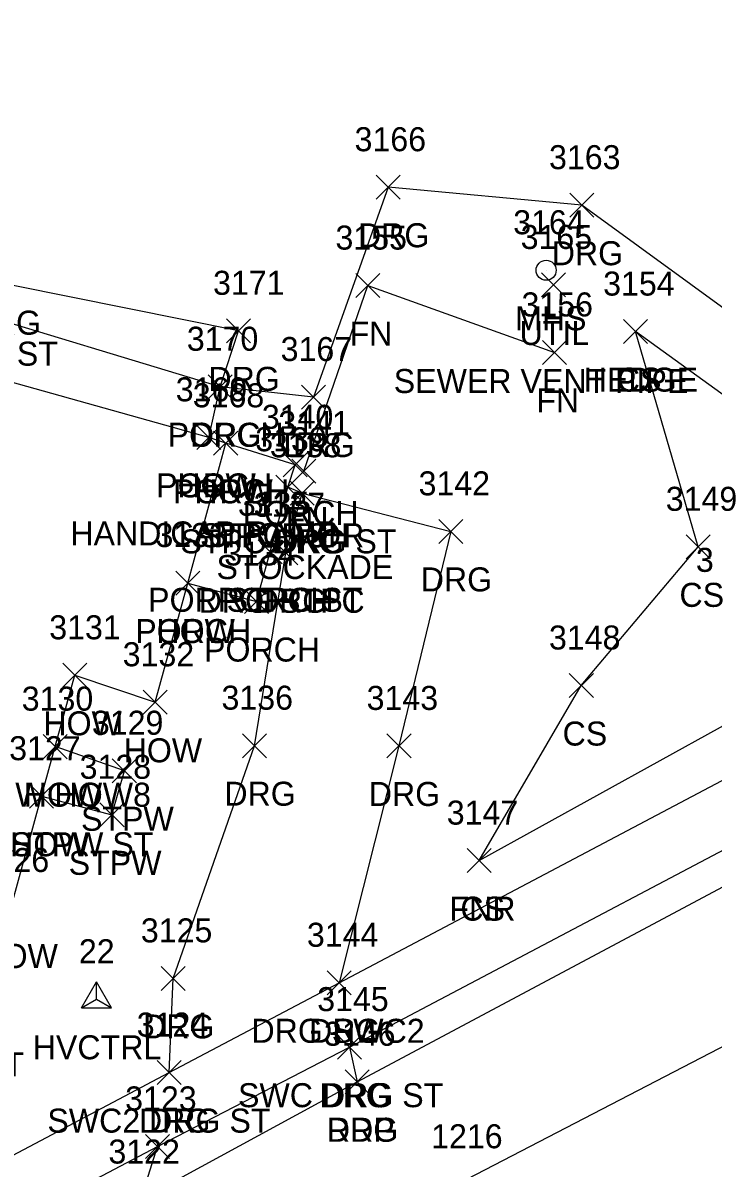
# Model space of a CAD drawing. Extents: x 1477930 to 1480780, y 774090 to 784647.
# Drawn here: x 1479519.5 to 1479576.9, y 774762.5 to 774857.9 of the extents above; entities that cross this region are included whole.
import ezdxf

# ---------------------------------------------------------------- set-up
doc = ezdxf.new("R2010")
doc.units = 0
for name, color, linetype in [('C_A', 7, 'Continuous'), ('C_I', 7, 'Continuous'), ('CPSM', 7, 'Continuous'), ('L_A', 7, 'Continuous'), ('L_C', 7, 'Continuous'), ('L_I', 7, 'Continuous'), ('L_TIC', 7, 'Continuous'), ('LAHR', 7, 'Continuous'), ('LBC', 7, 'Continuous'), ('LBF', 7, 'Continuous'), ('LELB', 7, 'Continuous'), ('LFNC', 7, 'Continuous'), ('P_A', 7, 'Continuous'), ('P_I', 7, 'Continuous'), ('P_TIC', 7, 'Continuous'), ('PET', 7, 'Continuous'), ('PRC', 7, 'Continuous'), ('R_A', 7, 'Continuous'), ('R_I', 7, 'Continuous'), ('R_TIC', 7, 'Continuous'), ('RDG', 7, 'Continuous'), ('RSW', 7, 'Continuous'), ('U_A', 7, 'Continuous'), ('U_C', 7, 'Continuous'), ('U_I', 7, 'Continuous'), ('UDEFAULT', 7, 'Continuous'), ('USMH', 7, 'Continuous')]:
    doc.layers.add(name, color=color, linetype=linetype)

msp = doc.modelspace()

# ---------------------------------------------------------------- linework, layer by layer
at = {"layer": 'CPSM'}
for p, q in [((1479524.324, 774775.847), (1479525.574, 774778.012)), ((1479526.824, 774775.847), (1479525.574, 774778.012)), ((1479525.574, 774776.568), (1479525.574, 774778.012)), ((1479524.324, 774775.847), (1479525.574, 774776.568)), ((1479525.574, 774776.568), (1479525.574, 774776.568)), ((1479525.574, 774776.568), (1479526.824, 774775.847)), ((1479524.324, 774775.847), (1479526.824, 774775.847))]:
    msp.add_line(p, q, dxfattribs=at)
at = {"layer": 'L_TIC'}
for points in [[(1479547.155, 774835.01), (1479549.155, 774837.01)], [(1479549.155, 774835.01), (1479547.155, 774837.01)], [(1479569.436, 774831.18), (1479571.436, 774833.18)], [(1479571.436, 774831.18), (1479569.436, 774833.18)], [(1479569.436, 774831.18), (1479571.436, 774833.18)], [(1479571.436, 774831.18), (1479569.436, 774833.18)], [(1479562.695, 774829.443), (1479564.695, 774831.443)], [(1479564.695, 774829.443), (1479562.695, 774831.443)], [(1479534.871, 774826.584), (1479536.871, 774828.584)], [(1479536.871, 774826.584), (1479534.871, 774828.584)], [(1479533.918, 774822.368), (1479535.918, 774824.368)], [(1479535.918, 774822.368), (1479533.918, 774824.368)], [(1479533.918, 774822.368), (1479535.918, 774824.368)], [(1479535.918, 774822.368), (1479533.918, 774824.368)], [(1479535.326, 774821.874), (1479537.326, 774823.874)], [(1479537.326, 774821.874), (1479535.326, 774823.874)], [(1479535.326, 774821.874), (1479537.326, 774823.874)], [(1479537.326, 774821.874), (1479535.326, 774823.874)], [(1479541.115, 774820.083), (1479543.115, 774822.083)], [(1479543.115, 774820.083), (1479541.115, 774822.083)], [(1479541.837, 774819.567), (1479543.837, 774821.567)], [(1479543.837, 774819.567), (1479541.837, 774821.567)], [(1479540.488, 774818.212), (1479542.488, 774820.212)], [(1479542.488, 774818.212), (1479540.488, 774820.212)], [(1479540.488, 774818.212), (1479542.488, 774820.212)], [(1479542.488, 774818.212), (1479540.488, 774820.212)], [(1479541.697, 774817.711), (1479543.697, 774819.711)], [(1479543.697, 774817.711), (1479541.697, 774819.711)], [(1479539.037, 774812.838), (1479541.037, 774814.838)], [(1479541.037, 774812.838), (1479539.037, 774814.838)], [(1479539.037, 774812.838), (1479541.037, 774814.838)], [(1479541.037, 774812.838), (1479539.037, 774814.838)], [(1479540.344, 774812.755), (1479542.344, 774814.755)], [(1479542.344, 774812.755), (1479540.344, 774814.755)], [(1479574.655, 774813.252), (1479576.655, 774815.252)], [(1479576.655, 774813.252), (1479574.655, 774815.252)], [(1479532.175, 774810.235), (1479534.175, 774812.235)], [(1479534.175, 774810.235), (1479532.175, 774812.235)], [(1479532.175, 774810.235), (1479534.175, 774812.235)], [(1479534.175, 774810.235), (1479532.175, 774812.235)], [(1479537.903, 774808.696), (1479539.903, 774810.696)], [(1479539.903, 774808.696), (1479537.903, 774810.696)], [(1479522.767, 774802.55), (1479524.767, 774804.55)], [(1479524.767, 774802.55), (1479522.767, 774804.55)], [(1479564.927, 774801.699), (1479566.927, 774803.699)], [(1479566.927, 774801.699), (1479564.927, 774803.699)], [(1479529.448, 774800.304), (1479531.448, 774802.304)], [(1479531.448, 774800.304), (1479529.448, 774802.304)], [(1479521.131, 774796.607), (1479523.131, 774798.607)], [(1479523.131, 774796.607), (1479521.131, 774798.607)], [(1479521.131, 774796.607), (1479523.131, 774798.607)], [(1479523.131, 774796.607), (1479521.131, 774798.607)], [(1479526.892, 774794.601), (1479528.892, 774796.601)], [(1479528.892, 774794.601), (1479526.892, 774796.601)], [(1479520, 774792.48), (1479522, 774794.48)], [(1479522, 774792.48), (1479520, 774794.48)], [(1479520, 774792.48), (1479522, 774794.48)], [(1479522, 774792.48), (1479520, 774794.48)], [(1479525.864, 774790.931), (1479527.864, 774792.931)], [(1479527.864, 774790.931), (1479525.864, 774792.931)], [(1479556.42, 774787.114), (1479558.42, 774789.114)], [(1479558.42, 774787.114), (1479556.42, 774789.114)], [(1479556.42, 774787.114), (1479558.42, 774789.114)], [(1479558.42, 774787.114), (1479556.42, 774789.114)]]:
    msp.add_lwpolyline(points, dxfattribs=at)
at = {"layer": 'LAHR'}
msp.add_lwpolyline([(1479584.946, 774821.703), (1479570.436, 774832.18)], dxfattribs=at)
at = {"layer": 'LBC'}
msp.add_lwpolyline([(1479518.439, 774784.168), (1479521, 774793.48), (1479522.131, 774797.607), (1479523.767, 774803.55), (1479530.448, 774801.304), (1479533.175, 774811.235), (1479536.326, 774822.874), (1479534.918, 774823.368), (1479506.67, 774831.282), (1479500.925, 774832.917)], dxfattribs=at)
at = {"layer": 'LBF'}
for points in [[(1479534.918, 774823.368), (1479535.871, 774827.584), (1479513.492, 774834.341), (1479508.389, 774836.064), (1479506.67, 774831.282)], [(1479533.175, 774811.235), (1479538.903, 774809.696), (1479540.037, 774813.838), (1479541.488, 774819.212), (1479542.115, 774821.083), (1479536.326, 774822.874)], [(1479540.037, 774813.838), (1479541.344, 774813.755), (1479542.697, 774818.711), (1479541.488, 774819.212)], [(1479521, 774793.48), (1479526.864, 774791.931), (1479527.892, 774795.601), (1479522.131, 774797.607)]]:
    msp.add_lwpolyline(points, dxfattribs=at)
at = {"layer": 'LELB'}
msp.add_lwpolyline([(1479557.42, 774788.114), (1479565.927, 774802.699), (1479575.655, 774814.252), (1479570.436, 774832.18)], dxfattribs=at)
at = {"layer": 'LFNC'}
for points in [[(1479542.837, 774820.567), (1479548.155, 774836.01), (1479563.695, 774830.443)], [(1479557.42, 774788.114), (1479582.544, 774801.997)]]:
    msp.add_lwpolyline(points, dxfattribs=at)
at = {"layer": 'P_TIC'}
for points in [[(1479546.258, 774768.694), (1479548.258, 774770.694)], [(1479548.258, 774768.694), (1479546.258, 774770.694)]]:
    msp.add_lwpolyline(points, dxfattribs=at)
at = {"layer": 'PET'}
msp.add_lwpolyline([(1479458.85, 774725.87), (1479463.751, 774725.492), (1479503.779, 774746.035), (1479529.26, 774759.882), (1479547.258, 774769.694), (1479593.154, 774794.187), (1479638.489, 774817.325), (1479672.216, 774835.12), (1479713.57, 774857.959), (1479753.195, 774879.739), (1479794.614, 774902.456), (1479830.334, 774920.879), (1479861.739, 774937.834), (1479877.763, 774946.853), (1479905.129, 774960.917), (1479936.646, 774977.614), (1479958.815, 774989.405), (1479973.001, 774995.932), (1480008.349, 775014.945)], dxfattribs=at)
at = {"layer": 'PRC'}
msp.add_lwpolyline([(1480015.885, 775005.874), (1479971.787, 774982.459), (1479929.137, 774959.029), (1479892.607, 774942.344), (1479860.439, 774925.31), (1479806.486, 774896.537), (1479658.454, 774815.543), (1479643.753, 774807.567), (1479597.617, 774782.971), (1479555.607, 774761.155), (1479513.424, 774740.323), (1479470.998, 774718.599), (1479432.732, 774701.096), (1479418.317, 774694.969), (1479344.833, 774660.922), (1479298.596, 774640.387), (1479262.123, 774624.397), (1479219.633, 774609.006), (1479186.742, 774593.828)], dxfattribs=at)
at = {"layer": 'R_TIC'}
for points in [[(1479548.849, 774843.203), (1479550.849, 774845.203)], [(1479550.849, 774843.203), (1479548.849, 774845.203)], [(1479564.978, 774841.708), (1479566.978, 774843.708)], [(1479566.978, 774841.708), (1479564.978, 774843.708)], [(1479536.401, 774831.244), (1479538.401, 774833.244)], [(1479538.401, 774831.244), (1479536.401, 774833.244)], [(1479534.871, 774826.584), (1479536.871, 774828.584)], [(1479536.871, 774826.584), (1479534.871, 774828.584)], [(1479542.643, 774825.727), (1479544.643, 774827.727)], [(1479544.643, 774825.727), (1479542.643, 774827.727)], [(1479541.697, 774817.711), (1479543.697, 774819.711)], [(1479543.697, 774817.711), (1479541.697, 774819.711)], [(1479554.073, 774814.54), (1479556.073, 774816.54)], [(1479556.073, 774814.54), (1479554.073, 774816.54)], [(1479540.344, 774812.755), (1479542.344, 774814.755)], [(1479542.344, 774812.755), (1479540.344, 774814.755)], [(1479537.727, 774796.688), (1479539.727, 774798.688)], [(1479539.727, 774796.688), (1479537.727, 774798.688)], [(1479549.751, 774796.668), (1479551.751, 774798.668)], [(1479551.751, 774796.668), (1479549.751, 774798.668)], [(1479530.959, 774777.305), (1479532.959, 774779.305)], [(1479532.959, 774777.305), (1479530.959, 774779.305)], [(1479544.779, 774776.94), (1479546.779, 774778.94)], [(1479546.779, 774776.94), (1479544.779, 774778.94)], [(1479544.779, 774776.94), (1479546.779, 774778.94)], [(1479546.779, 774776.94), (1479544.779, 774778.94)], [(1479545.637, 774771.577), (1479547.637, 774773.577)], [(1479547.637, 774771.577), (1479545.637, 774773.577)], [(1479545.637, 774771.577), (1479547.637, 774773.577)], [(1479547.637, 774771.577), (1479545.637, 774773.577)], [(1479530.618, 774769.459), (1479532.618, 774771.459)], [(1479532.618, 774769.459), (1479530.618, 774771.459)], [(1479530.618, 774769.459), (1479532.618, 774771.459)], [(1479532.618, 774769.459), (1479530.618, 774771.459)], [(1479546.258, 774768.694), (1479548.258, 774770.694)], [(1479548.258, 774768.694), (1479546.258, 774770.694)], [(1479529.653, 774763.307), (1479531.653, 774765.307)], [(1479531.653, 774763.307), (1479529.653, 774765.307)], [(1479529.653, 774763.307), (1479531.653, 774765.307)], [(1479531.653, 774763.307), (1479529.653, 774765.307)]]:
    msp.add_lwpolyline(points, dxfattribs=at)
at = {"layer": 'RDG'}
for points in [[(1479598.757, 774810.291), (1479588.804, 774826.084), (1479565.978, 774842.708), (1479549.849, 774844.203), (1479543.643, 774826.727), (1479535.871, 774827.584), (1479537.401, 774832.244), (1479514.065, 774836.924)], [(1479542.697, 774818.711), (1479555.073, 774815.54), (1479550.751, 774797.668), (1479545.779, 774777.94)], [(1479531.618, 774770.459), (1479531.959, 774778.305), (1479538.727, 774797.688), (1479541.344, 774813.755)], [(1479546.637, 774772.577), (1479547.258, 774769.694)], [(1479529.26, 774759.882), (1479530.653, 774764.307)]]:
    msp.add_lwpolyline(points, dxfattribs=at)
at = {"layer": 'RSW'}
for points in [[(1479454.048, 774732.201), (1479457.362, 774735.507), (1479461.547, 774734.407), (1479499.972, 774753.705), (1479531.618, 774770.459), (1479545.779, 774777.94), (1479596.697, 774804.864), (1479626.336, 774821.051), (1479665.838, 774842.34), (1479709.717, 774866.291), (1479748.232, 774887.235), (1479790.979, 774910.551), (1479825.884, 774929.42), (1479857.892, 774946.347), (1479880.805, 774958.363), (1479898.018, 774967.807), (1479932.308, 774985.558), (1479966.418, 775003.673), (1480005.027, 775023.737)], [(1479458.85, 774725.87), (1479459.6, 774730.001), (1479502.041, 774749.228), (1479530.653, 774764.307), (1479546.637, 774772.577), (1479592.504, 774796.776), (1479632.83, 774818.633), (1479668.395, 774838.36), (1479711.894, 774862.209), (1479750.542, 774883.441), (1479792.95, 774906.115), (1479828.149, 774924.963), (1479859.814, 774941.822), (1479882.293, 774953.428), (1479899.445, 774962.931), (1479935.388, 774981.771), (1479958.839, 774993.684), (1479967.683, 774998.521), (1480006.529, 775018.829)]]:
    msp.add_lwpolyline(points, dxfattribs=at)
at = {"layer": 'UDEFAULT'}
for points in [[(1479562.619, 774835.063), (1479564.619, 774837.063)], [(1479564.619, 774835.063), (1479562.619, 774837.063)]]:
    msp.add_lwpolyline(points, dxfattribs=at)
at = {"layer": 'USMH'}
for p, q in [((1479562.998, 774837.288), (1479562.998, 774837.288)), ((1479563.832, 774837.288), (1479563.832, 774837.288))]:
    msp.add_line(p, q, dxfattribs=at)
msp.add_circle((1479562.998, 774837.288), 0.833, dxfattribs=at)

# ---------------------------------------------------------------- texts
at = {"layer": 'C_A'}
msp.add_text('HVCTRL', height=2, dxfattribs=at).set_placement((1479520.267, 774771.568))
at = {"layer": 'C_I'}
msp.add_text('22', height=2, dxfattribs=at).set_placement((1479524.11, 774779.568))
at = {"layer": 'L_A'}
for s, p in [('STPW DRG', (1479506.546, 774831.924)), ('FN', (1479546.636, 774831.01)), ('DECK STPW ST', (1479502.303, 774829.341)), ('HEDGE', (1479566.136, 774827.18)), ('CS', (1479568.877, 774827.18)), ('FN', (1479562.175, 774825.443)), ('PORCH', (1479531.493, 774822.584)), ('PORCH', (1479530.54, 774818.368)), ('HOW', (1479532.304, 774818.368)), ('PORCH', (1479531.948, 774817.874)), ('HOW', (1479533.712, 774817.874)), ('PORCH', (1479537.737, 774816.083)), ('FN', (1479541.317, 774815.567)), ('STPC DRG ST', (1479532.563, 774813.711)), ('STPC POR', (1479534.189, 774814.212)), ('PORCH', (1479537.11, 774814.212)), ('POR STPC ST', (1479529.871, 774808.838)), ('DRG STPC', (1479534.076, 774808.755)), ('PORCH', (1479535.659, 774808.838)), ('CS', (1479574.096, 774809.252)), ('PORCH', (1479528.797, 774806.235)), ('HOW', (1479530.561, 774806.235)), ('PORCH', (1479534.525, 774804.696)), ('HOW', (1479521.153, 774798.55)), ('CS', (1479564.368, 774797.699)), ('HOW', (1479527.833, 774796.304)), ('STPW HOW8', (1479513.612, 774792.607)), ('HOW', (1479519.517, 774792.607)), ('STPW', (1479524.285, 774790.601)), ('HOW8 STPW ST', (1479509.654, 774788.48)), ('HOW', (1479518.386, 774788.48)), ('STPW', (1479523.258, 774786.931)), ('FNR', (1479554.955, 774783.114)), ('CS', (1479555.861, 774783.114)), ('HOW', (1479515.825, 774779.168)), ('HOW  STPW ST', (1479499.632, 774770.147))]:
    msp.add_text(s, height=2, dxfattribs=at).set_placement(p)
at = {"layer": 'L_C'}
for s, p in [('HANDICAP RAMP', (1479523.398, 774814.368)), ('STOCKADE', (1479535.561, 774811.567)), ('3 BOXES  - NO #', (1479575.461, 774812.167))]:
    msp.add_text(s, height=2, dxfattribs=at).set_placement(p)
at = {"layer": 'L_I'}
for s, p in [('3155', (1479545.463, 774839.01)), ('3154', (1479567.743, 774835.18)), ('3154', (1479567.743, 774835.18)), ('3156', (1479560.947, 774833.443)), ('3170', (1479533.092, 774830.584)), ('3169', (1479532.17, 774826.368)), ('3169', (1479532.17, 774826.368)), ('3168', (1479533.586, 774825.874)), ('3168', (1479533.586, 774825.874)), ('3140', (1479539.336, 774824.083)), ('3141', (1479540.711, 774823.567)), ('3139', (1479538.788, 774822.212)), ('3139', (1479538.788, 774822.212)), ('3138', (1479540.004, 774821.711)), ('3149', (1479572.954, 774817.252)), ('3135', (1479537.344, 774816.838)), ('3135', (1479537.344, 774816.838)), ('3137', (1479538.651, 774816.755)), ('3133', (1479530.482, 774814.235)), ('3133', (1479530.482, 774814.235)), ('3134', (1479536.21, 774812.696)), ('3131', (1479521.641, 774806.55)), ('3148', (1479563.234, 774805.699)), ('3132', (1479527.755, 774804.304)), ('3130', (1479519.352, 774800.607)), ('3130', (1479519.352, 774800.607)), ('3129', (1479525.191, 774798.601)), ('3127', (1479518.307, 774796.48)), ('3127', (1479518.307, 774796.48)), ('3128', (1479524.171, 774794.931)), ('3147', (1479554.727, 774791.114)), ('3147', (1479554.727, 774791.114)), ('3126', (1479515.691, 774787.168))]:
    msp.add_text(s, height=2, dxfattribs=at).set_placement(p)
at = {"layer": 'P_A'}
msp.add_text('RDP', height=2, dxfattribs=at).set_placement((1479544.746, 774764.694))
at = {"layer": 'P_I'}
for s, p in [('3146', (1479544.51, 774772.694)), ('1216', (1479553.426, 774764.155)), ('3122', (1479526.567, 774762.882))]:
    msp.add_text(s, height=2, dxfattribs=at).set_placement(p)
at = {"layer": 'R_A'}
for s, p in [('DRG', (1479547.337, 774839.203)), ('DRG', (1479563.466, 774837.708)), ('DRG', (1479534.889, 774827.244)), ('DRG', (1479533.359, 774822.584)), ('DRG', (1479541.132, 774821.727)), ('DRG', (1479540.185, 774813.711)), ('DRG', (1479552.561, 774810.54)), ('DRG', (1479538.832, 774808.755)), ('DRG', (1479536.216, 774792.688)), ('DRG', (1479548.239, 774792.668)), ('DRG', (1479529.447, 774773.305)), ('DRG SWC2', (1479538.472, 774772.94)), ('DRG', (1479543.267, 774772.94)), ('SWC DRG ST', (1479537.353, 774767.577)), ('DRG', (1479544.125, 774767.577)), ('SWC2 DRG ST', (1479521.484, 774765.459)), ('DRG', (1479529.106, 774765.459)), ('DRG', (1479544.746, 774764.694))]:
    msp.add_text(s, height=2, dxfattribs=at).set_placement(p)
at = {"layer": 'R_I'}
for s, p in [('3166', (1479547.054, 774847.203)), ('3163', (1479563.238, 774845.708)), ('3171', (1479535.275, 774835.244)), ('3170', (1479533.092, 774830.584)), ('3167', (1479540.903, 774829.727)), ('3138', (1479540.004, 774821.711)), ('3142', (1479552.38, 774818.54)), ('3137', (1479538.651, 774816.755)), ('3136', (1479535.979, 774800.688)), ('3143', (1479548.058, 774800.668)), ('3125', (1479529.266, 774781.305)), ('3144', (1479543.086, 774780.94)), ('3144', (1479543.086, 774780.94)), ('3145', (1479543.944, 774775.577)), ('3145', (1479543.944, 774775.577)), ('3124', (1479528.925, 774773.459)), ('3124', (1479528.925, 774773.459)), ('3146', (1479544.51, 774772.694)), ('3123', (1479527.96, 774767.307)), ('3123', (1479527.96, 774767.307)), ('3122', (1479526.567, 774762.882))]:
    msp.add_text(s, height=2, dxfattribs=at).set_placement(p)
at = {"layer": 'U_A'}
for s, p in [('MHS', (1479560.416, 774832.288)), ('UTIL', (1479560.784, 774831.063))]:
    msp.add_text(s, height=2, dxfattribs=at).set_placement(p)
at = {"layer": 'U_C'}
msp.add_text('SEWER VENT PIPE', height=2, dxfattribs=at).set_placement((1479550.312, 774827.063))
at = {"layer": 'U_I'}
for s, p in [('3164', (1479560.258, 774840.288)), ('3165', (1479560.878, 774839.063))]:
    msp.add_text(s, height=2, dxfattribs=at).set_placement(p)

doc.saveas('drawing.dxf')
